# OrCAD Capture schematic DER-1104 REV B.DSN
size Custom
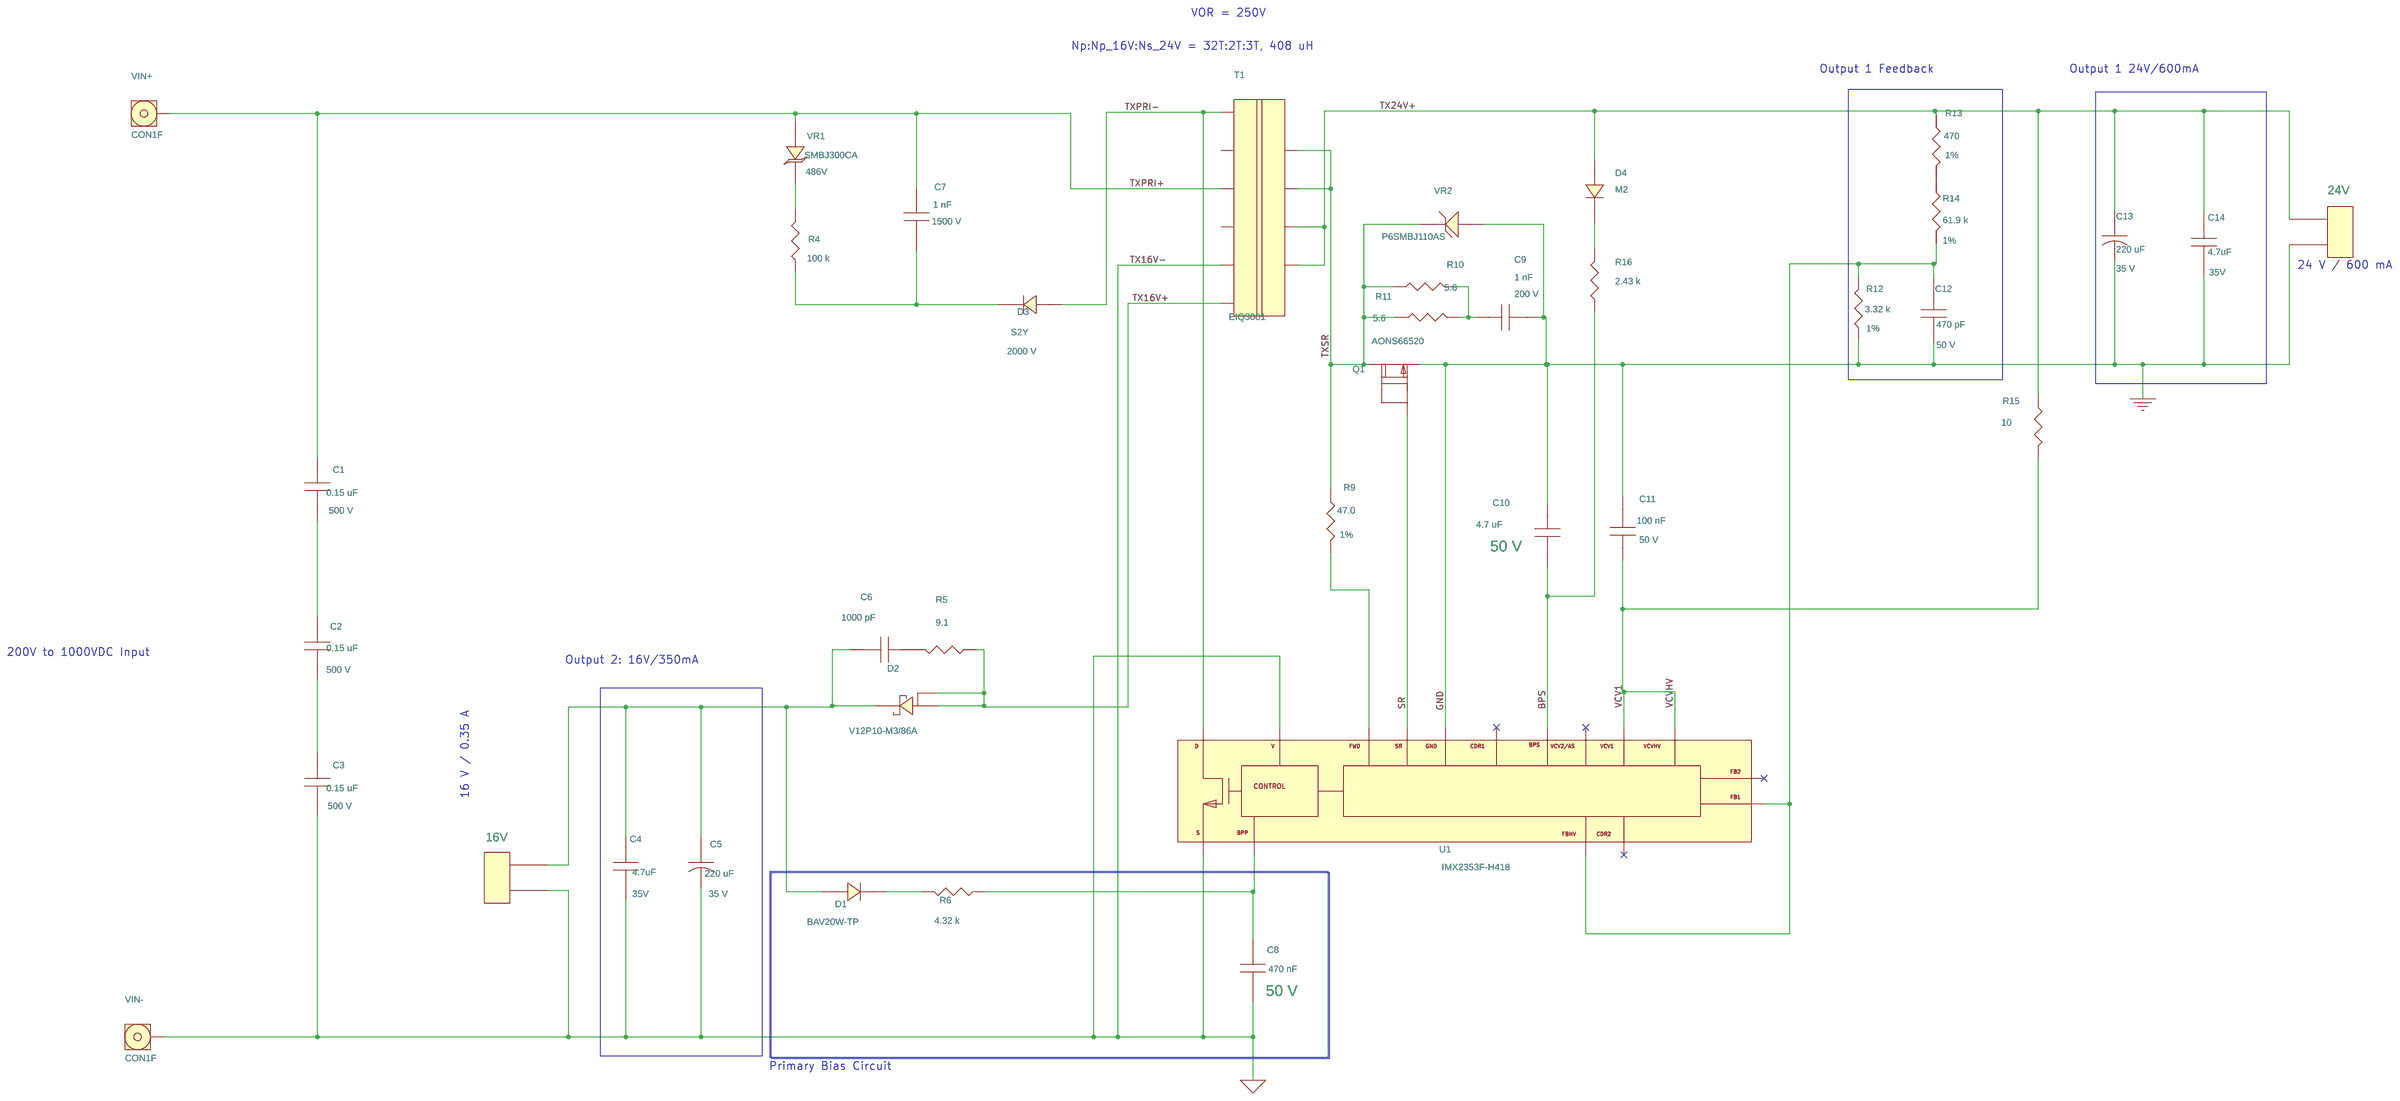
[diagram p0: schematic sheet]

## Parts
16V  CON2  [23839452]
24V  CON2  [23839452]
C1  0.15 uF  [pismc1210]
C2  0.15 uF  [pismc1210]
C3  0.15 uF  [pismc1210]
C4  4.7uF  [pismc1206]
C5  220 uF  [pismcpan1VA]
C6  1000 pF  [pismc0805]
C7  1 nF  [pismc1808]
C8  470 nF  [pismc0805]
C9  1 nF  [pismc1206]
C10  4.7 uF  [pismc1206]
C11  100 nF  [pismc0603]
C12  470 pF  [pismc0805]
C13  220 uF  [pismcpan1VA]
C14  4.7uF  [pismc1206]
D1  BAV20W-TP  [pi_sm_sod-123_12]
D2  V12P10-M3/86A  [pi_sm_d_to-277a]
D3  S2Y  [pismsmb]
D4  M2  [pismdo214ac12]
Q1  AONS66520  [pismpqfn5x6b]
R4  100 k  [pismr1206]
R5  9.1  [pismr0805]
R6  4.32 k  [pismr1206]
R9  47.0  [pismr0805]
R10  5.6  [pismr1206]
R11  5.6  [pismr1206]
R12  3.32 k  [pismr0603]
R13  470  [RC1206]
R14  61.9 k  [pismr1206]
R15  10  [pismr0603]
R16  2.43 k  [pismr1206]
T1  EIQ3001  [PISM_bobbin_EIQ3001]
U1  IMX2353F-H418  [InSOP-T28G_PWI]
VIN+  CON1F  [METZ_SM99S01VBNN00G7]
VIN-  CON1F  [METZ_SM99S01VBNN00G7]
VR1  SMBJ300CA  [DIO_DO214AA]
VR2  P6SMBJ110AS  [pismdo214aa12]

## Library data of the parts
16V 24V = CON2: Part Number: 35-00758-00
C1-C3 = CAP_NP_v2: Disp_Voltage: 500 V; Part Number: 20-02183-00; Voltage: 500 V
C4 C14 = CAP_NP_v2: Disp_Voltage: 35V; Part Number: 20-08590-00; Voltage: 35 V
C5 C13 = CAP_POL: Disp_Voltage: 35 V; Part Number: 24-00114-00; Voltage: 35 V
C6 = CAP_NP_v2: ALT_SYMBOLS: Unisem_RMCF0805UL; Disp_Voltage: 100 V; FPLIST: pismc0805,Unisem_RMCF0805UL; Part Number: 20-01617-00; Voltage: 100 V
C7 = CAP_NP_v2: Disp_Voltage: 1500 V; Part Number: 20-00577-00; Voltage: 1500 V
C8 = CAP_NP_v2: ALT_SYMBOLS: Unisem_RMCF0805UL; Disp_Voltage: 50 V; FPLIST: pismc0805,Unisem_RMCF0805UL; Part Number: 20-00896-00; Voltage: 50 V
C9 = CAP_NP_v2: Disp_Voltage: 200 V; Part Number: 24-00024-00; Voltage: 200 V
C10 = CAP_NP_v2: Disp_Voltage: 50 V; Part Number: 20-08752-00; Voltage: 50 V
C11 = CAP_NP_v2: ALT_SYMBOLS: Unisem_RMCF0603UL; Disp_Voltage: 50 V; Part Number: 20-01693-00; Voltage: 50 V
C12 = CAP_NP_v2: ALT_SYMBOLS: Unisem_RMCF0805UL; Disp_Voltage: 50 V; FPLIST: pismc0805,Unisem_RMCF0805UL; Part Number: 20-01672-00; Voltage: 50 V
D1 = DIODE: Part Number: 15-01109-00
D2 = DIODE_SCHOTTKY_TO-277A: Part Number: 15-00879-00
D3 = DIODE: Disp_Voltage: 2000 V; Part Number: 15-02116-00
D4 = DIODE: Disp_Voltage: 100 VDC; Part Number: 15-02305-00
Q1 = FET_N_SGD_123_4_5678: Part Number: 50-00481-00
R4 = R: Part Number: 05-01400-00
R5 = R: ALT_SYMBOLS: Unisem_RMCF0805UL; FPLIST: pismr0805,Unisem_RMCF0805UL; Part Number: 05-01470-00
R6 = R: Disp_Tol: 1%; Part Number: 05-00254-00
R9 = R: ALT_SYMBOLS: Unisem_RMCF0805UL; Disp_Tol: 1%; Part Number: 05-03476-00
R10 R11 = R: Part Number: 05-01298-00
R12 = R: ALT_SYMBOLS: Unisem_RMCF0603UL; Disp_Tol: 1%; Part Number: 05-01128-00
R13 = R: ALT_SYMBOLS: RC1206_HV; Disp_Power: 0.25 W; Disp_Tol: 1%; FPLIST: RC1206,RC1206_HV; Part Number: 05-06765-00
R14 = R: Disp_Tol: 1%; Part Number: 05-00365-00
R15 = R: ALT_SYMBOLS: Unisem_RMCF0603UL; FPLIST: pismr0603,Unisem_RMCF0603UL; Part Number: 05-01640-00
R16 = R: Disp_Tol: 1%; Part Number: 05-00230-00
T1 = BEIQ30_10P_GENERIC: Part Number: 25-01235-00
U1 = InnoMux2-EP_InSOP-T28G: Part Number: 10-01605-00
VIN+ VIN- = IC_PIN_1Pin_2pad: Part Number: 35-00756-00
VR1 = TVS_DIODE: Disp_Voltage: 486V; Part Number: 15-02256-00
VR2 = DIODE_ZENER: Disp_Voltage: 177 V; Part Number: 15-01833-00

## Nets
GND POWER: 24V.2 C9.2 C10.1 C11.2 C12.1 C13.2 C14.2 Q1.1(S) R12.1 U1.2 VR2.2
GND_SUPPLY: 16V.1 C3.2 C4.2 C5.2 C8.2 T1.5 U1.15 U1.18 VIN-.1
BPS: C10.2 R16.1 U1.6
SR: Q1.4(G) U1.9
TX16V+: D2.1(A1) D2.2(A2) R5.1 T1.6
TX24V+: 24V.1 C13.1 C14.1 D4.2(A) R13.1 R15.1 T1.7 T1.8
TXPRI+: C1.1 C7.1 T1.3 VIN+.1 VR1.2(A)
TXPRI-: D3.2(A) T1.1 U1.28
TXSR: Q1.5(D) R9.1 R10.1 R11.1 T1.9 T1.10 VR2.1
VCV1: C11.1 R15.2 U1.11 U1.13
N16959168: C12.2 R12.2 R14.2 U1.1 U1.8
N16971155: 16V.2 C4.1 C5.1 C6.2 D1.2(A) D2.3(Cathode)
N17016668: D1.1(K) R6.2
N17021924: C7.2 D3.1(K) R4.1
N17030469: C2.2 C3.1
N17037205: R13.2 R14.1
N17041030: R9.2 U1.10
N17051635: C8.1 R6.1 U1.16
N17059109: C6.1 R5.2
N17060192: R4.2 VR1.1(K)
N17061363: C1.2 C2.1
N17075641: C9.1 R10.2 R11.2
N17090457: D4.1(K) R16.2

Not connected (* = marked no-connect by the designer): Q1 2(S2) 3(S3) 6(D6) 7(D7) 8(D8); T1 2 4; U1 3* 5* 7* 12* 19; VIN+ 2; VIN- 2

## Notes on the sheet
- VOR = 250V
- Np:Np_16V:Ns_24V = 32T:2T:3T, 408 uH
- Output 1 Feedback
- Output 1 24V/600mA
- 24 V / 600 mA
- 200V to 1000VDC Input
- Output 2: 16V/350mA
- 16 V / 0.35 A
- Primary Bias Circuit
